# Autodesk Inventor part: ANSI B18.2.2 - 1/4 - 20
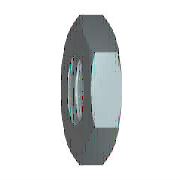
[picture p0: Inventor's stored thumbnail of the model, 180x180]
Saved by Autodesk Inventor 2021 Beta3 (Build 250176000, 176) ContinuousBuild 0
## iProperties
Created: 2013-02
Part Number: ANSI B18.2.2 - 1/4 - 20
Material: Generic
Description: Hex Nuts (Inch Series) Hex Jam Nut
Document SubType Name: Modeling
Standard: ANSI B18.2.2
Designer: John
Standard Revision: 1999
Standards Organization: ANSI
Language: en-US
Size Designation: 1/4 - 20
Categories: <MemberInstance><Categories><Category DisplayName="Fasteners" InternalName="e4da775c-781d-43d5-af7c-5136215cf5a6" Mnemonic="FSTN"><Category DisplayName="Nuts" I
Density: 1 g/cm^3
Appearance: Default
IsCustomPart: 0
Author: John
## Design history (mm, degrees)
sketch "Sketch1"
  geometry: L1 (-6.416, 0)-(-3.208, 5.556); L2 (-3.208, 5.556)-(3.208, 5.556); L3 (3.208, 5.556)-(6.416, 0); L4 (6.416, 0)-(3.208, -5.556); L5 (3.208, -5.556)-(-3.208, -5.556); L6 (-3.208, -5.556)-(-6.416, 0); 2 further points
  constraints: 12 end point, 1 coincident, 1 horizontal, 11 other
  dimensions: "d0" = 12.83161 distance of L3.end L1.start (= 1.1547 x SW)
extrude "Body" new body sketch "Sketch1" distance "d1" = 3.9624 (= KOH); taper "d2" = 0 deg
sketch "Sketch2"
  geometry: L1 (0, 3.208)-(0, 6.416) reference; L2 (0, 6.416)-(3.962, 6.416) reference; L3 (3.962, 3.208)-(3.962, 6.416) reference; L4 (-0.792, 0)-(4.755, 0) reference; L5 (0.401, 6.416)-(0, 5.556); L6 (3.562, 6.416)-(3.962, 5.556)
  constraints: 4 end point, 4 point on line
  dimensions: "d3" = 25 deg angle of L1 L5 (= ANG1); "d4" = 25 deg angle of L3 L6 (= ANG2); "d5" = 11.1125 diameter of L5.end L4 (= SW0); "d6" = 11.1125 diameter of L6.end L4 (= SW01)
revolve "Chamfer1" sketch "Sketch2" stored, may be unused: angle "d7" = 90 deg
sketch "Sketch3"
  geometry: A1 r 5.556 centre (0, 0) between (-2.778, -4.812) and (2.778, -4.812) reference; 1 further point
  constraints: 1 coincident
hole "Thread" sketch "Sketch3" at (0, 0) diameter "d25" = 4.9784; stored, may be unused: countersink angle "d29" = 82 deg, drill point angle "d31" = 118 deg; dims "d26" = 6, "d27" = 4, "d28" = 2, "d30" = 8
workaxis "Work Axis1"
workplane "Work Plane1"
body "Solid1"
chamfer "Chamfer2" distance "d8" = 0.68741 (= -0.5 x GD1 + 0.5 x NND); stored, may be unused: angle "d9" = 30 deg, second distance "d40" = 0.68741 (= -0.5 x GD1 + 0.5 x NND)
chamfer "Chamfer3" distance "d10" = 0.68741 (= -0.5 x GD1 + 0.5 x NND); stored, may be unused: angle "d11" = 30 deg, second distance "d41" = 0.68741 (= -0.5 x GD1 + 0.5 x NND)
other parameters: "ANG1" = 25 deg [user parameter; used in 1 equation term], "ANG2" = 25 deg [user parameter; used in 1 equation term], "NND" = 6.35 [user parameter; used in 4 equation terms], "KOH" = 3.9624 [user parameter; used in 1 equation term], "SW" = 11.1125 [user parameter; used in 4 equation terms], "SW0" = 11.1125 (= SW) [user parameter; used in 1 equation term], "SW01" = 11.1125 (= SW) [user parameter; used in 1 equation term], "GD1" = 4.97518 (computed from THREADDIA, PTC, TOA) [user parameter; used in 4 equation terms], "d13" = 0, "d14" = 0, "d39" = 0, "d42" = 0, "THREADDIA" = 6.35 [user parameter; used in 1 equation term], "TOA" = 30 deg [user parameter; used in 1 equation term], "PTC" = 1.27 (computed from TPU) [user parameter; used in 1 equation term], "E0" = 12.83494 (= 1.155 x SW) [user parameter]
